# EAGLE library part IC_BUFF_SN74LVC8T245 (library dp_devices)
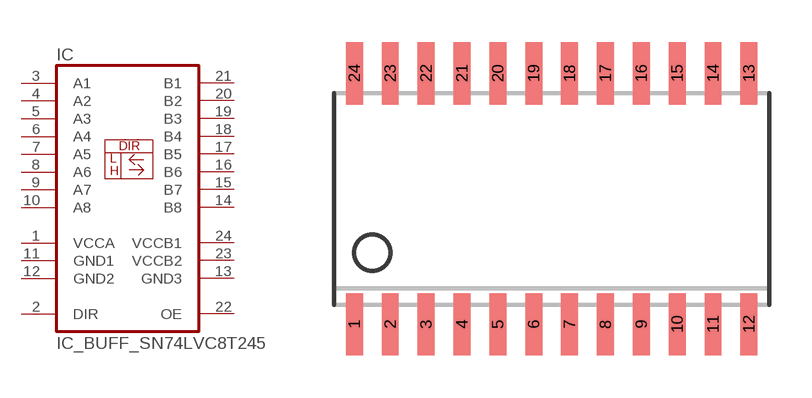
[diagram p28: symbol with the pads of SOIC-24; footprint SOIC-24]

Designator prefix IC

## IC_BUFF_SN74LVC8T245  [SOIC-24]
1  VCCA  pwr
2  DIR  in
3  A1
4  A2
5  A3
6  A4
7  A5
8  A6
9  A7
10  A8
11  GND1  pwr
12  GND2  pwr
13  GND3  pwr
14  B8
15  B7
16  B6
17  B5
18  B4
19  B3
20  B2
21  B1
22  OE  in
23  VCCB2  pwr
24  VCCB1  pwr

## Footprint SOIC-24 (pad centres in mm)
smd 0.6 x 2.2: 1 -6.985,-4.445; 2 -5.715,-4.445; 3 -4.445,-4.445; 4 -3.175,-4.445; 5 -1.905,-4.445; 6 -0.635,-4.445; 7 0.635,-4.445; 8 1.905,-4.445; 9 3.175,-4.445; 10 4.445,-4.445; 11 5.715,-4.445; 12 6.985,-4.445; 13 6.985,4.445; 14 5.715,4.445; 15 4.445,4.445; 16 3.175,4.445; 17 1.905,4.445; 18 0.635,4.445; 19 -0.635,4.445; 20 -1.905,4.445; 21 -3.175,4.445; 22 -4.445,4.445; 23 -5.715,4.445; 24 -6.985,4.445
